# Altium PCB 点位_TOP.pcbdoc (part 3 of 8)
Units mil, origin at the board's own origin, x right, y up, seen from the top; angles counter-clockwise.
Board outline 5129 x 4161 mil, 8 copper layers (Top Layer, GND1, 内层2, VCC, 内层4, Inner5, GND2, Bottom Layer); 288 components, 452 nets, 2040 pads, 1119 vias.
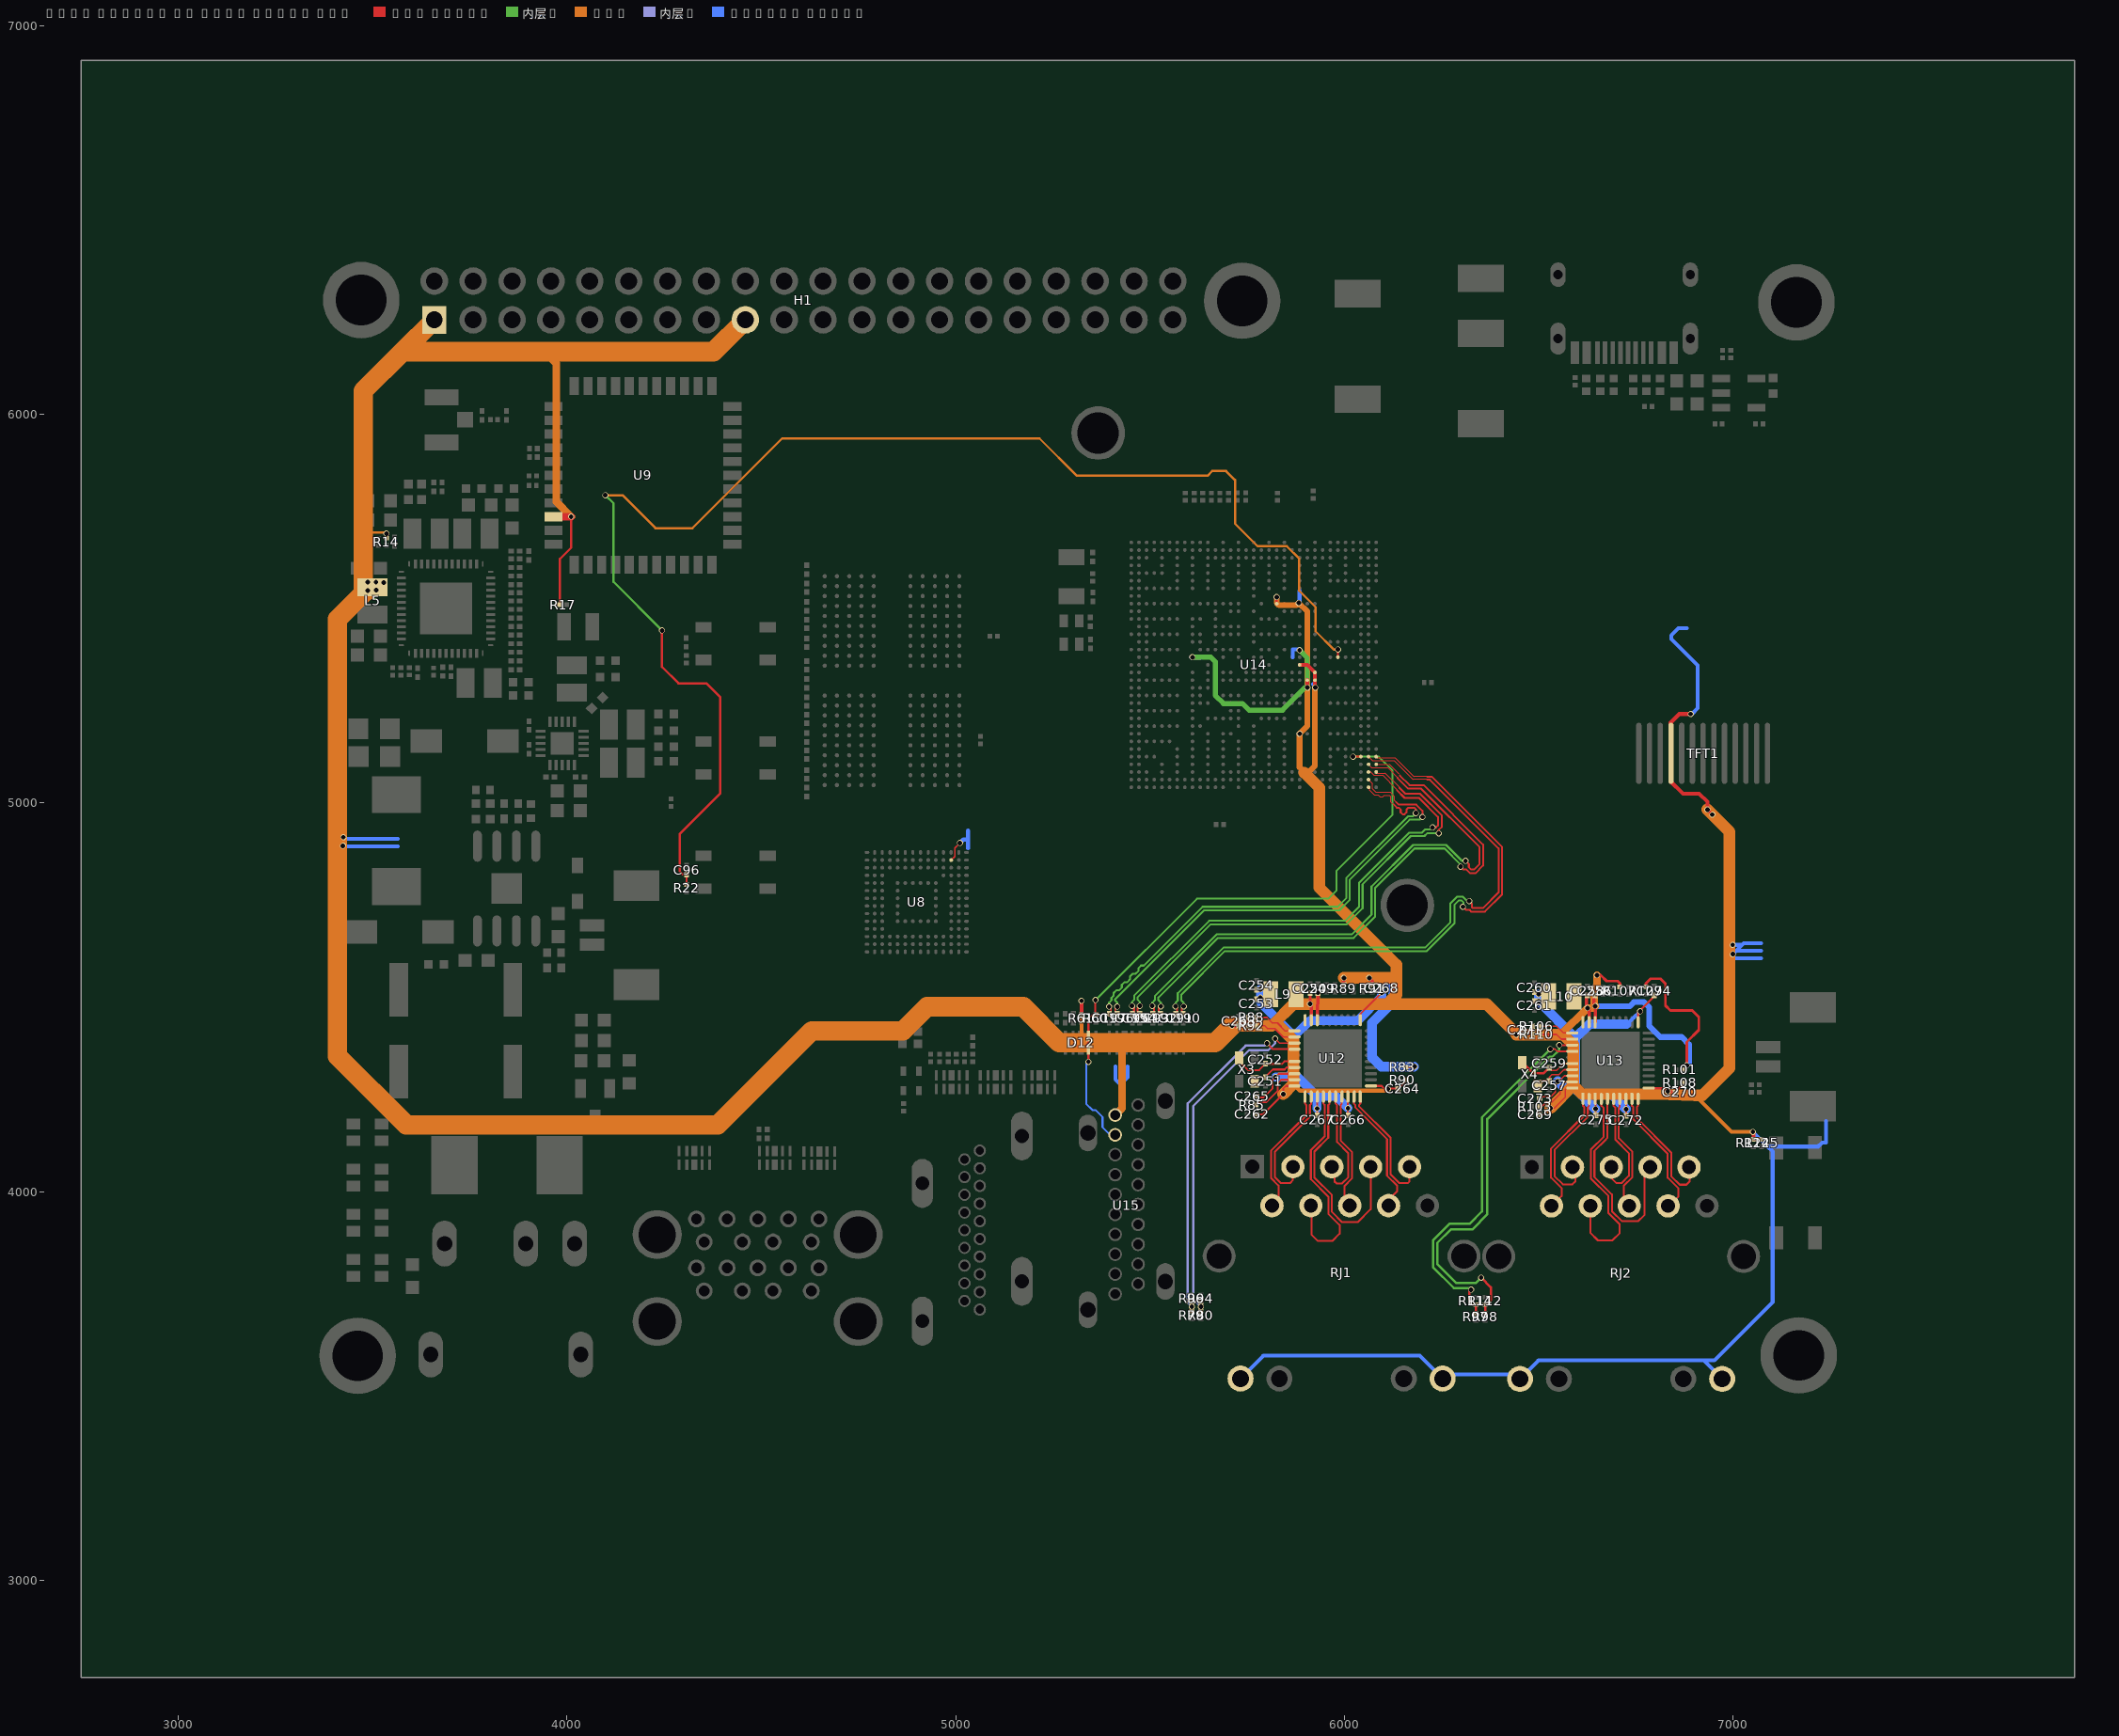
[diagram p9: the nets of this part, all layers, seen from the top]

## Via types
v1: diameter 15.75, hole 11.8, Top Layer to Bottom Layer, 496 vias
v2: diameter 15.7, hole 11.8, Top Layer to Bottom Layer, 335 vias
v3: diameter 15.75, hole 11.81, Top Layer to Bottom Layer, 279 vias
v4: diameter 24, hole 12, Top Layer to Bottom Layer, 9 vias

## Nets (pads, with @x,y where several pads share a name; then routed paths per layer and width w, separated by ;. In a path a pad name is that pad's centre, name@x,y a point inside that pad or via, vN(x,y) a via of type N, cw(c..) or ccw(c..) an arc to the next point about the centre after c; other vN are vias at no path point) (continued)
EDP-HPD: D12.4 D12.7 R60.2 U14.C29 U15.18 | length 1646.6
  Top Layer w5: v1(5341.7,4334) D12.4@5341.7,4365.67 D12.7@5341.7,4400.33 5341.7,4444.7 5354,4457 R60.2@5359.51,4457 ; v1(5360,4493) 5359.51,4492.51 R60.2@5359.51,4457 ; R60.2@5361,4455.51 R60.2@5359.51,4457 ; v1(6022.57,5119.25) U14.C29@6042.57,5119.25
  内层2 w5: v1(5360,4493) 5621,4754 5959,4754 5980,4775 5980,4826 6124,4970 6124,5084 6088.75,5119.25 v1(6022.57,5119.25)
  Bottom Layer w5: v1(5341.7,4334) 5336,4328.3 5336,4226 5352,4210 5360,4210 5378,4192 5378,4166 5397.8,4146.2 U15.18@5410.5,4146.2
EDP-TX0N: C191.1 U14.B29 | length 1595.3
  Top Layer w3: U14.B29@6062.19,5119.21 6072.01,5109.39 6127.61,5109.39 6176,5061 6213,5061 6214,5060
  Top Layer w5: v1(5566,4477) 5570,4473 5570,4461 C191.1@5566.6,4457.6 ; 6214,5060 6220,5060 6397,4883 6397,4770 6356.63,4729.63 6330.23,4729.63 6328.47,4731.4 6328.47,4740.59 v1(6321.13,4747.92)
  内层2 w5: v1(5566,4477) 5566,4486.37 5571.6,4491.97 5571.6,4510.35 5689.27,4628.02 6208.29,4628.02 6273,4692.73 6273,4742 6290,4759 6305,4759 6316.08,4747.92 v1(6321.13,4747.92)
EDP-TX0P: C190.1 U14.A29 | length 1590.8
  Top Layer w3: U14.A29@6081.89,5119.21 6084.71,5116.39 6130.61,5116.39 6179,5068 6213,5068
  Top Layer w5: C190.1@5585.6,4457.6 5582,4461.21 5582,4472 v1(5587,4477) ; 6213,5068 6224.73,5068 6406,4886.73 6406,4765 6361.63,4720.63 6326.51,4720.63 6322.1,4725.03 6312.91,4725.03 v1(6304.87,4733.08)
  内层2 w5: v1(5587,4477) 5587,4485.58 5580.61,4491.97 5580.61,4506.61 5693,4619 6212,4619 6283,4690 6283,4738 6294,4749 6302,4749 6307,4744 6307,4735.21 v1(6304.87,4733.08)
EDP-TX1N: C193.1 U14.B30 | length 1542
  Top Layer w3: U14.B30@6062.19,5099.51 6071.7,5090 6113,5090 6134.5,5068.5 6134.5,5067.5
  Top Layer w5: v1(5506,4478) 5511,4473 5511,4461 C193.1@5507.6,4457.6 ; 6136.64,5064.64 6164.27,5037 6197.59,5037 6348,4886.59 6348,4843 6333.72,4828.72 6326.65,4828.72 6320.34,4835.03 6320.34,4842.66 v1(6312,4851)
  内层2 w5: v1(5506,4478) 5506,4486.37 5512.6,4492.97 5512.6,4503.35 5671.27,4662.02 6019.02,4662.02 6070,4713 6070,4785 6177.02,4892.02 6261.73,4892.02 6302.75,4851 v1(6312,4851)
EDP-TX1P: C192.1 U14.A30 | length 1534.9
  Top Layer w3: U14.A30@6081.94,5099.55 6083.49,5098 6116.73,5098 6140.86,5073.86
  Top Layer w5: C192.1@5526.6,4457.6 5523,4461.21 5523,4472 v1(5528,4477) ; 6143,5071 6168,5046 6204,5046 6357,4893 6357,4839 6337,4819 6323.64,4819 6313.97,4828.66 6306.34,4828.66 v1(6299,4836)
  内层2 w5: v1(5528,4477) 5528,4486.58 5521.61,4492.97 5521.61,4499.61 5675,4653 6024,4653 6079,4708 6079,4781.25 6180.75,4883 6258,4883 6299,4842 v1(6299,4836)
EDP-TX2N: C195.1 U14.B31 | length 1301.6
  Top Layer w3: U14.B31@6062.19,5079.81 6067.41,5079.81 6077.21,5070.01 6100,5070.01 6134,5036 6134,5034.27 6135.64,5032.64
  Top Layer w5: v1(5454,4478) 5459,4473 5459,4462 C195.1@5454.6,4457.6 ; 6135.64,5032.64 6155.27,5013 6192,5013 6241,4964 6241,4942 6236,4937 v2(6227,4937)
  内层2 w5: v1(5454,4478) 5454,4488.37 5459.49,4493.87 5459.49,4504.24 5652.27,4697.02 6002.02,4697.02 6038,4733 6038,4794.73 6167.28,4924.02 6200.02,4924.02 6208,4932 6222,4932 v2(6227,4937)
EDP-TX2P: C194.1 U14.A31 | length 1303.9
  Top Layer w3: U14.A31@6081.89,5079.81 6084.69,5077.01 6104.67,5077.01 6142,5039.75 6142,5039
  Top Layer w5: v1@5470.61,4478 v1(5474,4478) 5468.02,4472.02 5468.02,4463.19 C194.1@5473.6,4457.6 ; 6142,5039 6157,5024 6195,5024 6251,4968 6251,4939.14 6243,4931.14 v2(6243,4922)
  内层2 w5: v1(5474,4478) 5474,4488.37 5468.51,4493.87 5468.51,4500.51 5656,4688 6006,4688 6047,4729 6047,4790.98 6171.02,4915 6206,4915 6213,4922 v2(6243,4922)
EDP-TX3N: C197.1 U14.B33 | length 1264.8
  Top Layer w3: U14.B33@6062.19,5040.41 6065.09,5037.51 6065.09,5033.45 6077.52,5021.02 6087.2,5021.02 6092.2,5016.02 6099.2,5016.02 6103.18,5020 6116,5020 6119.98,5016.02 6119.98,5003.29 6127.64,4995.64
  Top Layer w4: v1(5395,4476) 5400,4471 5400,4462 C197.1@5395.6,4457.6
  Top Layer w5: 6127.64,4995.64 6135.27,4988 6140,4988 6145,4983 6145,4976 6150,4971 6155,4971 6160,4976 6160,4983 6165,4988 6180,4988 6184,4984 v2(6184,4974)
  内层2 w5: v1(5395,4476) 5395,4486.37 5400.99,4492.37 5400.99,4498.6 5406.4,4504.01 5406.4,4511.08 5413.47,4518.15 5420.54,4518.15 5427.62,4525.22 5427.62,4532.3 5434.69,4539.37 5441.76,4539.37 5448.83,4546.44 5448.83,4553.51 5455.9,4560.58 5462.97,4560.58 5470.04,4567.65 5470.04,4574.72 5477.11,4581.79 5484.18,4581.79 5635.41,4733.02 5983.02,4733.02 6005,4755 6005,4806.75 6164.25,4966 6176,4966 v2(6184,4974)
EDP-TX3P: C196.1 U14.B32 | length 1261.6
  Top Layer w3: U14.B32@6062.19,5060.11 6072.2,5050.1 6072.2,5044.58 6072.09,5044.47 6072.09,5036.35 6080.42,5028.02 6118.1,5028.02 6127,5019.12 6127,5019 6129,5017 6129,5007 6134,5002
  Top Layer w4: C196.1@5415.6,4457.6 5411,4462.21 5411,4471 v1(5416,4476)
  Top Layer w5: 6134,5002 6140,4996 6185,4996 6201,4980 v2(6201,4964)
  内层2 w5: v1(5416,4476) 5416,4486.37 5410.01,4492.37 5410.01,4494.87 5639.14,4724 5987,4724 6014,4751 6014,4803 6168,4957 6194,4957 v2(6201,4964)
EMMC-VDDI: U8.C2 | length 122.7
  Top Layer w4: U8.C2@4988.59,4853.27 4998,4862.68 4998,4884 v1(5011,4897)
  Bottom Layer w10: v1(5011,4897) 5020,4906 5032,4906 ; 5032,4884 5032,4906 ; 5032,4929 5032,4906
FEL: C96.2 R22.2 U14.F16 | length 3642.7
  Top Layer w5: U14.F16@5983.52,5375.16 v1(5983.52,5395.16)
  Top Layer w6: v2(4245,5444) 4245,5350 4287,5308 4359,5308 4394,5273 4394,5024 4290,4920 4290,4824.62 4298.62,4816 C96.2@4308,4816 R22.2@4308,4790.51
  内层2 w6: v2(4099,5792) 4120,5771 4120,5569 v2(4245,5444)
  VCC w6: v2(4099,5792) 4143,5792 4228,5707 4323,5707 4554,5938 5216,5938 5312,5842 5648,5842 5660,5854 5696,5854 5719,5831 5719,5719 5777,5661 5852,5661 5884,5629 5884,5546 5926,5504 5926,5441.81 5972.64,5395.16 v1(5983.52,5395.16)
GM0_DVDD10: C253.1 C254.1 C265.1 C266.1 C267.1 C268.2 L9.2 U12.3 U12.8 U12.21 U12.38 | length 1119.3
  Top Layer w5: C265.1@5772.5,4246 5776.5,4242 5792,4242 5815,4265 5815,4287 v1(5822.89,4294.89) 5831.6,4303.6 U12.38@5871.6,4303.6 ; C267.1@5930,4196.5 v1(5930,4214) 5930,4244 U12.3@5930.6,4244.6 ; U12.8@6009.4,4244.6 v1(6009.4,4215) 6009.4,4197.1 C266.1@6010,4196.5 ; U12.21@6040.9,4441.4 6040.9,4456.9 6096,4512 v1(6096,4512.5)
  Bottom Layer w23: v1(5784,4521) v1(5784,4499) 5784,4487 5872,4399 5872,4313.21 ; v1(5822.89,4294.89) 5853.67,4294.89 5872,4313.21 ; 5874,4403 5911,4440 6034,4440 6096,4502 v1(6096,4512.5) ; v1(5930,4214) 5930,4245 ; v1(6009.4,4215) 5979.4,4245 5930,4245 ; 5872,4313.21 5872,4303 5930,4245
GM0_INTB: R88.2 U12.31 | length 114.6
  Top Layer w4: R88.2@5771.51,4449 5772.51,4448 5801,4448 5815,4434 5828,4434 5848.1,4413.9 U12.31@5871.6,4413.9
GM0_LED0: R92.1 U12.32 | length 112.1
  Top Layer w4: R92.1@5771.51,4427 5795.51,4427 5802.51,4420 5821,4420 5842.9,4398.1 U12.32@5871.6,4398.1
GM0_LED1: R80.2 R94.2 U12.33 | length 892.8
  Top Layer w4: v2(5822,4394) 5833.6,4382.4 U12.33@5871.6,4382.4
  Top Layer w6: R80.2@5631,3691.51 v2(5631,3703.92) R94.2@5631,3715.49
  内层4 w6: v2(5631,3703.92) 5611,3723.92 5611,4220 5755,4364 5804,4364 5822,4382 v2(5822,4394)
GM0_LED2: R79.1 R96.2 U12.34 | length 897
  Top Layer w5: v2(5801,4382) 5816.4,4366.6 U12.34@5871.6,4366.6
  Top Layer w6: R79.1@5608,3691.51 v2(5608,3703.69) R96.2@5608,3715.49
  内层4 w6: v2(5608,3703.69) 5597,3714.69 5597,4227 5746,4376 5795,4376 v2(5801,4382)
GM0_MDIN0: RJ1.P3 U12.2 | length 336.5
  Top Layer w5: RJ1.P3@5867.8,4064.16 5867.8,4029.8 5860,4022 5837,4022 5821,4038 5821,4102.25 5911.51,4192.76 5911.51,4222.96 5914.9,4226.35 U12.2@5914.9,4244.6
GM0_MDIN1: RJ1.P7 U12.5 | length 564.9
  Top Layer w5: U12.5@5962.1,4244.6 5962.1,4226.35 5958.76,4223.01 5958.76,4139.01 5923,4103.25 5923,4036 5968.02,3990.98 5968.02,3947.98 5994,3922 6035,3922 6067.8,3954.8 RJ1.P7@6067.8,4064.16
GM0_MDIN2: RJ1.P6 U12.7 | length 307.6
  Top Layer w5: U12.7@5993.6,4244.6 5993.6,4226.35 5990.26,4223.01 5990.26,4131.74 6019.64,4102.36 6019.64,4033.89 6000.38,4014.62 6000.38,3977.68 RJ1.P6@6013.9,3964.16
GM0_MDIN3: RJ1.P9 U12.10 | length 332.4
  Top Layer w5: U12.10@6040.9,4244.6 6040.9,4226.35 6037.51,4222.96 6037.51,4220.46 6119,4138.97 6119,4045 6142,4022 6163,4022 6167.8,4026.8 RJ1.P9@6167.8,4064.16
GM0_MDIP0: RJ1.P2 U12.1 | length 334
  Top Layer w5: RJ1.P2@5813.9,3964.16 5830.62,3980.88 5830.62,4015.62 5811.98,4034.27 5811.98,4105.98 5902.49,4196.49 5902.49,4222.96 5899.1,4226.35 U12.1@5899.1,4244.6
GM0_MDIP1: RJ1.P4 U12.4 | length 562
  Top Layer w5: RJ1.P4@5913.9,3964.16 5916,3962.06 5916,3889 5932,3873 5969,3873 5988,3892 5988,3914 5959,3943 5959,3987.25 5913.98,4032.27 5913.98,4106.98 5949.74,4142.74 5949.74,4223.01 5946.4,4226.35 U12.4@5946.4,4244.6
GM0_MDIP2: RJ1.P5 U12.6 | length 306.3
  Top Layer w5: RJ1.P5@5967.8,4064.16 5975,4056.96 5975,4026 5980,4021 5994,4021 6010.62,4037.62 6010.62,4098.62 5981.24,4128.01 5981.24,4223.01 5977.9,4226.35 U12.6@5977.9,4244.6
GM0_MDIP3: RJ1.P8 U12.9 | length 335.5
  Top Layer w5: U12.9@6025.1,4244.6 6025.1,4226.35 6028.49,4222.96 6028.49,4216.73 6109.98,4135.23 6109.98,4041.27 6136,4015.25 6136,4001 6113.9,3978.9 RJ1.P8@6113.9,3964.16
GM0_REGOUT: L9.1 U12.30
GM0_RSET: R85.2 U12.39 | length 137.4
  Top Layer w5: R85.2@5772.51,4223 5779.51,4230 5799,4230 5829,4260 5829,4279.49 5837.41,4287.9 U12.39@5871.6,4287.9
GM0_XTAL_IN: C252.2 U12.36 X3.1 | length 167.3
  Top Layer w5: X3.1@5729,4342 5729,4336 5752,4313 5781,4313 C252.2@5797,4329 5840,4329 5846.1,4335.1 U12.36@5871.6,4335.1
GM0_XTAL_OUT: C251.2 U12.37 X3.3 | length 118.1
  Top Layer w5: X3.3@5769,4282 5782,4295 C251.2@5797,4295 5816.4,4314.4 5846.4,4314.4 5851.4,4319.4 U12.37@5871.6,4319.4
GM1_DVDD10: C260.1 C261.1 C272.1 C273.1 C274.1 C275.2 L10.2 U13.3 U13.8 U13.21 U13.38 | length 1030.9
  Top Layer w4: C273.1@6502.5,4240 6506.5,4244 6531,4244 6543,4256 6543,4275 6566.11,4298.11 U13.38@6586.51,4298.11
  Top Layer w5: U13.3@6645.51,4239.11 6646,4238.62 v1(6646,4213) 6646,4197 C275.2@6647,4196 ; U13.8@6724.31,4239.11 6725,4238.42 v1(6725,4212.42) C272.1@6725,4195.5
  Top Layer w6: U13.21@6755.81,4435.91 6755.81,4461.31 C274.1@6800,4505.5
  Bottom Layer w10: 6726,4431 ccw(c6182.51,5042.49) v1(6761,4464)
  Bottom Layer w25: v1(6500,4508) v1(6500,4489.39) 6594,4395.39 ; v1(6549,4284) 6568,4265 6594,4265 ; v1(6646,4213) 6608,4251 ; v1(6725,4212.42) 6686.42,4251 6608,4251 ; 6726,4431 6629.61,4431 6594,4395.39 ; 6594,4265 6594,4395.39 ; 6594,4265 6608,4251
GM1_DVDDRG: C249.1 C250.1 C256.1 C258.1 C262.1 C263.1 C264.1 C269.1 C270.1 C271.1 H1.1 H1.17 L5.1 R14.1 R17.2 R61.1 R83.1 R88.1 R89.2 R90.1 R91.2 R92.2 R101.1 R106.1 R107.2 R108.1 R109.2 R110.2 R124.2 R125.2 RJ1.11 RJ1.14 RJ2.11 RJ2.14 TFT1.10 U9.9 U12.11 U12.28 U12.29 U12.40 U13.11 U13.28 U13.29 U13.40 U14.AE16 U14.J18 U14.J19 U14.K19 U14.L9 U14.L15 U14.L17 U14.L26 U14.P9 U15.20 | length 18139.1
  Top Layer w4: v1(6442,4404) 6463.5,4404 C271.1@6464,4404.5 6483.99,4404.5 R110.2@6484.49,4405 R106.1@6484.49,4426 ; C269.1@6502.5,4198 6513,4198 v1(6530,4215) 6540,4215 6568,4243 6568,4263 6571.61,4266.61 U13.40@6586.51,4266.61 ; R101.1@6872.51,4314 6881,4322.49 v1(6881,4325)
  Top Layer w5: C263.1@5729,4427.5 R92.2@5748.97,4427.5 ; R88.1@5752.49,4449 R92.2@5752.49,4431.02 ; C262.1@5774,4199 5791,4199 v2(5843,4251) 5843,4265 5850.1,4272.1 U12.40@5871.6,4272.1 ; U12.11@6068.4,4272.1 6095.9,4272.1 6103,4265 C264.1@6138.5,4265 6159.51,4286.01 R90.1@6159.51,4288 ; R83.1@6159.51,4320 6179,4320 v1(6181,4322) ; R92.2@5748.97,4427.5 R92.2@5752.49,4431.02 ; R92.2@5748.97,4427.5 5751.99,4427.5 R92.2@5752.49,4427 R92.2@5752.49,4431.02
  Top Layer w6: R17.2@3980.49,5510 3982,5511.51 3982,5628 4011,5657 v2(4011,5736.7) ; U14.P9@5826.04,5512.95 v1(5826.04,5529.95) ; R89.2@5998,4533.51 R89.2@5999,4532.51 ; U13.11@6783.31,4266.61 6823.39,4266.61 v1(6832,4258) 6851.5,4258 cw(c6943.92,4165.58) 6864,4269 ccw(c6847.99,4289.72) R108.1@6872.51,4280.53
  Top Layer w7: v2(6650,4557) 6660,4557 6675,4542 6702.98,4542 6709,4535.98 R107.2@6709,4526.51 ; R109.2@6776,4526.51 6776,4536 6788,4548 6813,4548 6826,4535 6826,4479 6839,4466 6895,4466 6912,4449 6912,4416 6881,4385 v1(6881,4325)
  Top Layer w8: C250.1@5912,4511.5 v1(5912,4483) 5914.9,4480.1 U12.29@5914.9,4441.4 ; U12.28@5930.6,4441.4 5930.6,4480.6 5932,4482 v2(5932,4511.5) ; C258.1@6625,4505.5 6623,4503.5 6623,4475 6629.81,4468.19 U13.29@6629.81,4435.91 ; U13.28@6645.51,4435.91 v1(6645.51,4477.49) 6642,4481 6642,4498 C256.1@6646,4502
  Top Layer w10: R14.1@3536,5681.51 v1(3536,5693) ; R61.1@5323,4455.51 5324,4456.51 v2(5324,4491) ; v1(5711,4427) 5728.5,4427 C263.1@5729,4427.5 ; U14.L17@5885.1,5355.47 5904.77,5355.47 U14.J18@5924.46,5335.78 U14.J19@5924.46,5316.1 5924.46,5297.54 v2(5925,5297) ; U14.K19@5904.78,5316.1 5904.78,5297.22 v2(5905,5297) ; R89.2@5998,4533.51 5998,4549 v2(5999,4550) ; v2@6065,4548 6072,4541 R91.2@6072,4532.51 ; v2(6891,5229) 6862,5229 6839.32,5206.32 6839.32,5055.68 6871,5024 6913,5024 6934,5003 v2(6934,4983) v2(6946.75,4970.25) ; v1(7051,4154) 7052.62,4152.38 R124.2@7052.62,4134.97 R125.2@7073.62,4134.97
  Top Layer w20: U9.9@3965.94,5736.7 v2(4011,5736.7)
  内层2 w13: v2(5609.5,5375.16) 5656.84,5375.16 5668,5364 5668,5277 5689,5256 5738,5256 5755,5239 5841,5239 5899,5297 v2(5905,5297) 5905,5373 v2(5885,5393)
  VCC w6: 3476,5695.88 3533.12,5695.88 v1(3536,5693)
  VCC w10: 5323.62,4383 5324,4383.38 v2(5324,4491) ; 5869,4277 5886,4260 6108,4260 v2(6112,4264) ; 5931.89,4483 5932,4483.11 v2(5932,4511.5) ; v1(6832,4258) 6892,4258 6902,4248 6996,4154 v1(7051,4154)
  VCC w15: v1(5826.04,5529.95) 5826.04,5514.96 5832,5509 5877,5509 v2(5883,5515) 5905,5493 v2(5905,5297) 5905,5198.22 v1(5885.09,5178.3) 5885,5178.22 5885,5092 5894,5083 ; 5908,5079 5924,5095 5924,5296 v2(5925,5297)
  VCC w20: 3939,6165 3943,6161 3973,6131 3973,5774.7 v2(4011,5736.7) ; U15.20@5410.5,4197.4 5428,4214.9 5428,4379.05 5424.05,4383 ; 6557.3,4404 6557.3,4404.46 v1(6625.42,4472.58) 6640.59,4472.58 v1(6645.51,4477.49) 6643,4480 6643,4521.72 6650,4528.72 v2(6650,4557)
  VCC w30: v1(5711,4427) 5813.57,4427 5815.91,4429.34 ; v2(5843,4251) 5869,4277 5869,4390 5829.66,4429.34 5815.91,4429.34 ; 5897,5078 5935.63,5039.37 5935.63,4782.37 6134,4584 6134,4538.28 ; v2(5999,4550) v2(6064.35,4550) 6122.28,4550 6134,4538.28 ; 6119,4492 6134,4507 6134,4538.28 ; v1(6530,4215) 6589,4274 ; v1@6832.33,4251 6801,4251 ; v2(6934,4983) v2(6946.75,4970.25) 6991,4926 6991,4318 6921,4248 6902,4248 6801,4251 ; 5815.91,4429.34 5869.57,4483 v1(5912,4483) 5931.89,4483 6366,4483 6442,4407 v1(6442,4404) 6557.3,4404 6563.26,4404 6589,4378.26 6589,4274 ; 6589,4274 6612,4251 6801,4251
  VCC w50: 3476,5552 3476,5695.88 3476,6060 3577,6161 ; v1(3488,5547) 3484.03,5547 3410,5472.97 3410,4349 3587,4172 4388.56,4172 4630.56,4414 4865,4414 4927,4476 5174,4476 5267,4383 5323.62,4383 5424.05,4383 5667,4383 v1(5711,4427) ; H1.1@3659,6243 3577,6161 ; H1.17@4459,6243 4377,6161 3943,6161 3577,6161
  Bottom Layer w10: v2(3424,4890) 3425.78,4888.23 3564.97,4888.23 ; v2(3425,4912) 3428.88,4908.12 3564.77,4908.12 3564.97,4907.91 ; U15.20@5410.5,4197.4 5424,4210.9 5424,4276 ; 5411.1,4322.16 5411.1,4288.9 5424,4276 ; 5442.11,4322.1 5442.11,4294.11 5424,4276 ; RJ1.11@5733,3519.16 5791.84,3578 6194.16,3578 RJ1.14@6253,3519.16 6263.84,3530 6440.4,3530 RJ2.11@6452,3518.4 6499.6,3566 6924.4,3566 ; 5867,5375 5867,5395 5883,5395 v2(5885,5393) ; v2(5883,5515) 5885,5517 5885,5546 ; 5885,5161 5885.09,5161.09 v1(5885.09,5178.3) ; 5904,5276 5904,5296 v2(5905,5297) 5904.22,5297.78 5904.22,5320.22 ; 5919.22,5306.22 5925,5300.44 v2(5925,5297) 5925,5276 ; 6881,5449.5 6859.26,5449.5 6840.91,5431.15 6840.91,5422.09 6909,5354 6909,5244 6894,5229 v2(6891,5229) ; RJ2.14@6972,3518.4 6924.4,3566 ; v2(6999,4635) 7023,4635 ; v1(7051,4154) 7089,4116 ; 7072.02,4600.26 7005.74,4600.26 6997,4609 7007.94,4619.94 ; 7072.02,4619.94 7007.94,4619.94 ; 7072.02,4639.62 7027.62,4639.62 7023,4635 ; 7239,4181.39 7239,4126.5 7229.5,4126.5 7219,4116 7089,4116 ; 6924.4,3566 6952,3566 7102,3716 7102,4103 7089,4116 ; 7007.94,4619.94 7023,4635
  Bottom Layer w13: v2@5607.38,5374.75 5607.63,5375 5630,5375
  Bottom Layer w15: v1(6645.51,4477.49) 6646,4477 6734,4477 6745,4488 6771,4488 6784,4475 6784,4427 6813,4398 6868,4398 6887,4379 6887,4331 v1(6881,4325)
  Bottom Layer w25: v2(6064.35,4550) 6065.35,4551 6097,4551 ; 6101,4550 6126,4525 6126,4489 6071,4434 6071,4346 6095,4322 v1@6179.07,4322
  other v1: 3510,5548 3529,5567 3488,5568 3509,5568
  other v2: 6999.28,4611.28
GM1_INTB: R106.2 U13.31 | length 90.3
  Top Layer w4: R106.2@6503.51,4426 6546,4426 6563.59,4408.41 U13.31@6586.51,4408.41
GM1_LED0: R110.1 U13.32 | length 88.1
  Top Layer w4: R110.1@6503.51,4405 6504,4404.51 6545.49,4404.51 6557.39,4392.61 U13.32@6586.51,4392.61
GM1_LED1: R98.2 R112.2 U13.33 | length 1011.5
  Top Layer w4: v2(6553.09,4376.91) U13.33@6586.51,4376.91
  Top Layer w6: v1(6352,3779) 6377,3754 6377,3721 6365.61,3709.61 R112.2@6362.37,3709.61 R98.2@6362.37,3687.63
  内层2 w6: v1(6352,3779) 6338,3765 6288,3765 6239,3814 6239,3867.95 6274.05,3903 6329,3903 6368,3942 6368,4187 6528,4347 6535,4347 6553.09,4365.09 v2(6553.09,4376.91)
GM1_LED2: R97.1 R114.2 U13.34 | length 972.2
  Top Layer w4: v2(6529.98,4367) 6542,4367 6547.89,4361.11 U13.34@6586.51,4361.11
  Top Layer w6: v1(6326,3748) 6322,3744 6322,3716 6328.39,3709.61 R114.2@6338.37,3709.61 R97.1@6338.37,3687.63
  内层2 w6: v1(6326,3748) 6322,3752 6282,3752 6228,3806 6228,3875 6271,3918 6323,3918 6354,3949 6354,4191.02 v2(6529.98,4367)
GM1_MDIN0: RJ2.P3 U13.2 | length 340.9
  Top Layer w5: RJ2.P3@6586.8,4063.4 6594,4056.2 6594,4026 6587,4019 6562,4019 6541,4040 6541,4107.25 6626.41,4192.66 6626.41,4217.47 6629.81,4220.86 U13.2@6629.81,4239.11
GM1_MDIN1: RJ2.P7 U13.5 | length 556
  Top Layer w5: 6674.66,4136.33 6672.02,4133.69 ; U13.5@6677.01,4239.11 6676.43,4238.54 6676.43,4138.09 6672.02,4133.69 ; RJ2.P7@6786.8,4063.4 6772.4,4049 6772.4,3940.81 6755.4,3923.81 6714.4,3923.81 6688.42,3949.8 6688.42,3992.8 6643.4,4037.81 6643.4,4105.06 6672.02,4133.69
GM1_MDIN2: RJ2.P6 U13.7 | length 306
  Top Layer w5: U13.7@6708.51,4239.11 6708.51,4218.34 6706.16,4216 6706.16,4137.56 6741.02,4102.71 6741.02,4037.27 6719,4015.25 6719,3977.3 RJ2.P6@6732.9,3963.4
GM1_MDIN3: RJ2.P9 U13.10 | length 334.5
  Top Layer w5: U13.10@6755.81,4239.11 6755.81,4220.86 6752.41,4217.47 6752.41,4189.59 6841.02,4100.98 6841.02,4039.98 6863,4018 6880,4018 6888,4026 6888,4062.2 RJ2.P9@6886.8,4063.4
GM1_MDIP0: RJ2.P2 U13.1 | length 334.8
  Top Layer w5: RJ2.P2@6532.9,3963.4 6533.4,3963.4 6559,3989 6559,4009.25 6531.98,4036.27 6531.98,4110.98 6617.4,4196.4 6617.4,4217.47 6614.01,4220.86 U13.1@6614.01,4239.11
GM1_MDIP1: RJ2.P4 U13.4 | length 555.7
  Top Layer w5: RJ2.P4@6632.9,3963.4 6632.9,3894.31 6652.4,3874.81 6689.4,3874.81 6708.4,3893.81 6708.4,3915.81 6679.4,3944.81 6679.4,3989.06 6634.38,4034.08 6634.38,4108.8 6667.42,4141.83 6667.42,4215 6661.31,4221.11 U13.4@6661.31,4239.11 ; RJ2.P4@6634.3,3965.97 RJ2.P4@6636.4,3963.87
GM1_MDIP2: RJ2.P5 U13.6 | length 302.6
  Top Layer w5: RJ2.P5@6686.8,4063.4 6685,4061.6 6685,4037 6700,4022 6713,4022 6732,4041 6732,4099 6697.15,4133.85 6697.15,4216 6692.81,4220.34 U13.6@6692.81,4239.11
GM1_MDIP3: RJ2.P8 U13.9 | length 337.3
  Top Layer w5: U13.9@6740.01,4239.11 6740.01,4220.86 6743.4,4217.47 6743.4,4185.85 6832,4097.25 6832,4036.25 6859,4009.25 6859,3987 6835.4,3963.4 RJ2.P8@6832.9,3963.4
GM1_REGOUT: L10.1 U13.30
GM1_RSET: R103.2 U13.39 | length 123.4
  Top Layer w4: R103.2@6500.51,4219 6508,4219 6520,4231 6535.09,4231 6555,4250.91 6555,4270 6567.41,4282.41 U13.39@6586.51,4282.41
GM1_XTAL_IN: C259.2 U13.36 X4.1 | length 154.7
  Top Layer w4: C259.2@6527,4319 6534,4312 6546,4312 6563.61,4329.61 U13.36@6586.51,4329.61
  Top Layer w6: X4.1@6459,4332 6486,4305 6513,4305 C259.2@6527,4319
GM1_XTAL_OUT: C257.2 U13.37 X4.3 | length 110.1
  Top Layer w4: C257.2@6527,4285 6527,4294 6534,4301 6552,4301 6564.91,4313.91 U13.37@6586.51,4313.91
  Top Layer w6: X4.3@6499,4272 6512,4285 C257.2@6527,4285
